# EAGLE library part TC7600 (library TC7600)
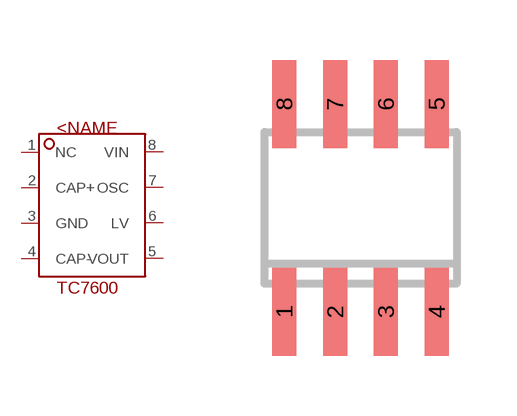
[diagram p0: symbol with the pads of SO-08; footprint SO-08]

Designator prefix -

## TC7600  [SO-08]
1  NC  nc
2  CAP+  out
3  GND  out
4  CAP-  in
5  VOUT  out
6  LV  out
7  OSC  in
8  VIN  in

## Footprint SO-08 (pad centres in mm)
Small Outline Narrow Plastic Gull Wing 150-mil body, package type SN
smd 0.6 x 2.2: 1 -1.905,-2.6; 2 -0.635,-2.6; 3 0.635,-2.6; 4 1.905,-2.6; 5 1.905,2.6; 6 0.635,2.6; 7 -0.635,2.6; 8 -1.905,2.6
